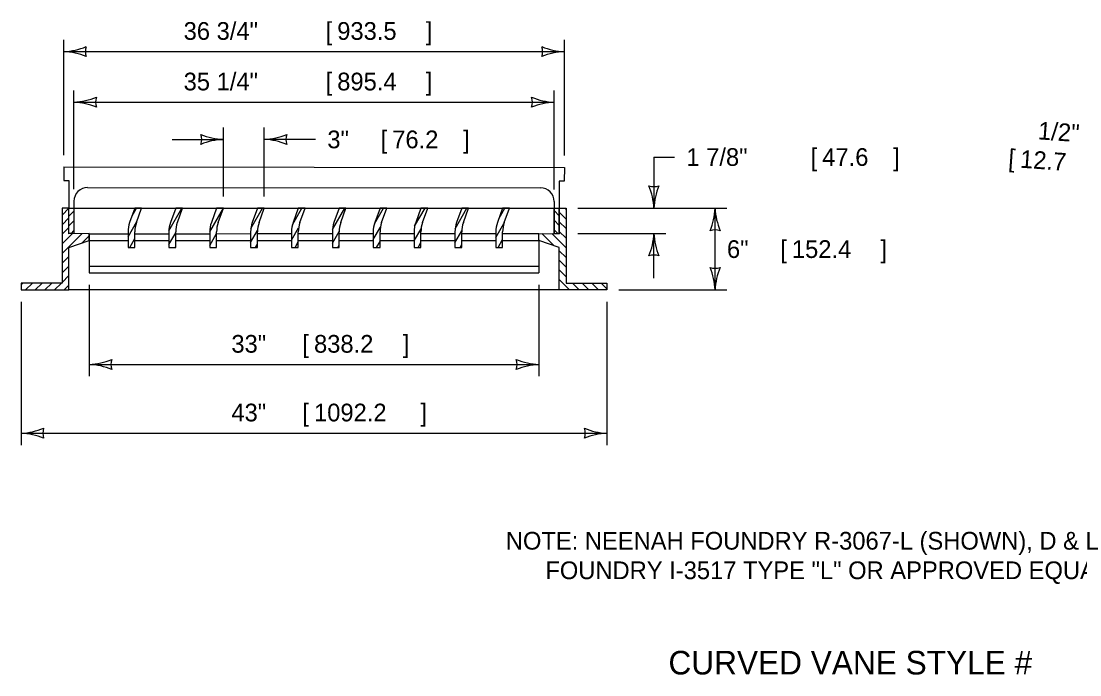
# Model space of a CAD drawing. Extents: x 49991.4 to 50057, y 49987.6 to 50011.4.
# Drawn here: x 50047.642 to 50051.224, y 49994.48 to 49996.693 of the extents above; entities that cross this region are included whole.
import ezdxf

# ---------------------------------------------------------------- set-up
doc = ezdxf.new("R2010")
doc.units = 0
for name, color, linetype in [('Level 1', 7, 'Continuous'), ('Level 2', 7, 'Continuous'), ('Level 3', 7, 'Continuous')]:
    doc.layers.add(name, color=color, linetype=linetype)

msp = doc.modelspace()

# ---------------------------------------------------------------- linework, layer by layer
at = {"layer": 'Level 1'}
for p, q in [((50047.7862, 49996.1991), (50049.4801, 49996.1976)), ((50047.7862, 49996.1991), (50047.7862, 49996.153)), ((50049.4801, 49996.1976), (50049.48, 49996.1515)), ((50047.7862, 49996.153), (50047.8035, 49996.153)), ((50047.8035, 49996.153), (50047.8035, 49996.0594)), ((50049.48, 49996.1515), (50049.4628, 49996.1516)), ((50049.4628, 49996.1516), (50049.4628, 49996.0594)), ((50047.8669, 49996.1299), (50049.3995, 49996.1286)), ((50047.8208, 49996.0838), (50047.8208, 49996.0594)), ((50049.4455, 49996.0825), (50049.4455, 49995.9742)), ((50047.7804, 49996.0364), (50047.8034, 49996.0594)), ((50047.8035, 49996.0321), (50047.8208, 49996.0494)), ((50047.8208, 49996.0594), (50049.4455, 49996.0594)), ((50047.8208, 49996.0594), (50047.8208, 49995.9742)), ((50048.0165, 49996.0313), (50048.0327, 49996.0594)), ((50048.142, 49995.9829), (50048.1862, 49996.0594)), ((50048.2802, 49995.9796), (50048.3263, 49996.0594)), ((50048.4192, 49995.9909), (50048.4587, 49996.0594)), ((50048.5598, 49996.0033), (50048.5922, 49996.0594)), ((50048.6954, 49995.9873), (50048.737, 49996.0594)), ((50048.8373, 49996.0064), (50048.8679, 49996.0594)), ((50048.9736, 49995.9987), (50049.0086, 49996.0594)), ((50049.1104, 49995.9896), (50049.1507, 49996.0594)), ((50049.2583, 49996.0238), (50049.2788, 49996.0594)), ((50049.4455, 49996.0513), (50049.4628, 49996.034)), ((50049.4628, 49996.046), (50049.4858, 49996.023)), ((50049.482, 49996.0594), (50049.4858, 49996.0556)), ((50047.7804, 49996.0038), (50047.8035, 49996.0268)), ((50047.7804, 49995.9712), (50047.8035, 49995.9942)), ((50047.8035, 49995.9995), (50047.8208, 49996.0168)), ((50048.0037, 49995.963), (50048.0335, 49996.0146)), ((50048.5568, 49995.9519), (50048.5809, 49995.9936)), ((50048.8334, 49995.9535), (50048.8578, 49995.9959)), ((50049.2482, 49995.9602), (50049.2755, 49996.0075)), ((50049.4455, 49996.0187), (50049.4628, 49996.0014)), ((50049.4628, 49996.0134), (50049.4858, 49995.9904)), ((50047.7804, 49995.906), (50047.8483, 49995.9738)), ((50047.7804, 49995.9386), (50047.815, 49995.9732)), ((50047.8108, 49995.9742), (50047.8208, 49995.9842)), ((50047.8491, 49995.9421), (50047.8726, 49995.9656)), ((50047.8726, 49995.973), (50048.0039, 49995.9731)), ((50047.8726, 49995.973), (50047.8726, 49995.8404)), ((50048.0095, 49995.9269), (50048.0267, 49995.9568)), ((50048.027, 49995.9731), (50048.142, 49995.9732)), ((50048.142, 49995.9367), (50048.165, 49995.9766)), ((50048.165, 49995.9732), (50048.2802, 49995.9733)), ((50048.2802, 49995.9335), (50048.3033, 49995.9734)), ((50048.3033, 49995.9733), (50048.4187, 49995.9734)), ((50048.4185, 49995.9437), (50048.4417, 49995.9837)), ((50048.4416, 49995.9734), (50048.5568, 49995.9735)), ((50048.5798, 49995.9735), (50048.6951, 49995.9736)), ((50048.6951, 49995.9407), (50048.7181, 49995.9806)), ((50048.7181, 49995.9736), (50048.8335, 49995.9737)), ((50048.8564, 49995.9738), (50048.9718, 49995.9739)), ((50048.9716, 49995.9492), (50048.9953, 49995.9902)), ((50048.9949, 49995.9739), (50049.1101, 49995.974)), ((50049.1099, 49995.9426), (50049.133, 49995.9826)), ((50049.1331, 49995.974), (50049.2484, 49995.9741)), ((50049.2714, 49995.9741), (50049.3937, 49995.9742)), ((50049.4044, 49995.9741), (50049.446, 49995.9325)), ((50049.4376, 49995.9734), (50049.4858, 49995.9252)), ((50049.4455, 49995.9861), (50049.4587, 49995.973)), ((50049.4628, 49995.9808), (50049.4858, 49995.9578)), ((50047.8726, 49995.9499), (50048.0037, 49995.9499)), ((50048.0267, 49995.9499), (50048.142, 49995.9499)), ((50048.1629, 49995.9269), (50048.165, 49995.9305)), ((50048.165, 49995.9499), (50048.2802, 49995.9499)), ((50048.3031, 49995.9269), (50048.3033, 49995.9273)), ((50048.3033, 49995.9499), (50048.4185, 49995.9499)), ((50048.4354, 49995.9269), (50048.4416, 49995.9375)), ((50048.4416, 49995.9499), (50048.5568, 49995.9499)), ((50048.569, 49995.9269), (50048.5798, 49995.9457)), ((50048.5798, 49995.9499), (50048.6951, 49995.9499)), ((50048.7137, 49995.9269), (50048.7181, 49995.9345)), ((50048.7181, 49995.9499), (50048.8334, 49995.9499)), ((50048.8446, 49995.9269), (50048.8564, 49995.9473)), ((50048.8564, 49995.9499), (50048.9716, 49995.9499)), ((50048.9853, 49995.9269), (50048.9947, 49995.943)), ((50048.9947, 49995.9499), (50049.1099, 49995.9499)), ((50049.1274, 49995.9269), (50049.133, 49995.9364)), ((50049.133, 49995.9499), (50049.2482, 49995.9499)), ((50049.2556, 49995.9269), (50049.2712, 49995.954)), ((50049.2712, 49995.9499), (50049.3937, 49995.9499)), ((50049.3937, 49995.9522), (50049.3971, 49995.9488)), ((50049.3937, 49995.9499), (50049.3937, 49995.8404)), ((50047.7804, 49995.8734), (50047.8035, 49995.8965)), ((50049.4628, 49995.9157), (50049.4858, 49995.8926)), ((50047.7804, 49995.8408), (50047.8035, 49995.8639)), ((50047.8726, 49995.8635), (50049.3937, 49995.8635)), ((50049.4628, 49995.8831), (50049.4858, 49995.86)), ((50049.4628, 49995.8505), (50049.4858, 49995.8274)), ((50047.7804, 49995.8082), (50047.8035, 49995.8313)), ((50047.8726, 49995.8404), (50049.3937, 49995.8404)), ((50049.4628, 49995.8179), (50049.4979, 49995.7828)), ((50047.6422, 49995.8003), (50047.6477, 49995.8059)), ((50047.6573, 49995.7828), (50047.6803, 49995.8059)), ((50047.6899, 49995.7828), (50047.7129, 49995.8059)), ((50047.7224, 49995.7828), (50047.7455, 49995.8059)), ((50047.755, 49995.7828), (50047.7781, 49995.8059)), ((50047.7876, 49995.7828), (50047.8035, 49995.7987)), ((50049.4628, 49995.7828), (50047.8035, 49995.7828)), ((50049.4628, 49995.7853), (50049.4653, 49995.7828)), ((50049.5074, 49995.8059), (50049.5305, 49995.7828)), ((50049.54, 49995.8059), (50049.563, 49995.7828)), ((50049.5726, 49995.8059), (50049.5956, 49995.7828)), ((50049.6052, 49995.8059), (50049.6241, 49995.7869))]:
    msp.add_line(p, q, dxfattribs=at)
for points in [[(50047.8035, 49995.7828), (50047.8035, 49995.9269), (50047.8726, 49995.9499), (50047.8726, 49995.9743), (50047.8035, 49995.973), (50047.8035, 49996.0594), (50047.7804, 49996.0594), (50047.7804, 49995.8059), (50047.6422, 49995.8059), (50047.6422, 49995.7828)], [(50047.8035, 49996.0594), (50047.8208, 49996.0594), (50047.8208, 49995.9742), (50047.8035, 49995.9742)], [(50049.4628, 49995.7828), (50049.4628, 49995.9269), (50049.3937, 49995.9499), (50049.3937, 49995.9743), (50049.4628, 49995.973), (50049.4628, 49996.0594), (50049.4858, 49996.0594), (50049.4858, 49995.8059), (50049.6241, 49995.8059), (50049.6241, 49995.7828)], [(50049.4455, 49996.0594), (50049.4628, 49996.0594), (50049.4628, 49995.973), (50049.4455, 49995.973)]]:
    msp.add_lwpolyline(points, close=True, dxfattribs=at)
for points in [[(50048.0323, 49996.0113), (50048.0498, 49996.0594), (50048.0267, 49996.0594), (50048.0267, 49996.0594), (50048.0092, 49996.0113)], [(50048.1706, 49996.0113), (50048.1881, 49996.0594), (50048.165, 49996.0594), (50048.165, 49996.0594), (50048.1475, 49996.0113)], [(50048.3088, 49996.0113), (50048.3263, 49996.0594), (50048.3033, 49996.0594), (50048.3033, 49996.0594), (50048.2858, 49996.0113)], [(50048.4471, 49996.0113), (50048.4646, 49996.0594), (50048.4416, 49996.0594), (50048.4416, 49996.0594), (50048.4241, 49996.0113)], [(50048.5854, 49996.0113), (50048.6029, 49996.0594), (50048.5798, 49996.0594), (50048.5798, 49996.0594), (50048.5624, 49996.0113)], [(50048.7237, 49996.0113), (50048.7412, 49996.0594), (50048.7181, 49996.0594), (50048.7181, 49996.0594), (50048.7006, 49996.0113)], [(50048.8619, 49996.0113), (50048.8794, 49996.0594), (50048.8564, 49996.0594), (50048.8564, 49996.0594), (50048.8389, 49996.0113)], [(50049.0002, 49996.0113), (50049.0177, 49996.0594), (50048.9947, 49996.0594), (50048.9947, 49996.0594), (50048.9772, 49996.0113)], [(50049.1385, 49996.0113), (50049.156, 49996.0594), (50049.133, 49996.0594), (50049.133, 49996.0594), (50049.1155, 49996.0113)], [(50049.2768, 49996.0113), (50049.2943, 49996.0594), (50049.2712, 49996.0594), (50049.2712, 49996.0594), (50049.2537, 49996.0113)], [(50048.0037, 49995.9798), (50048.0037, 49995.9269), (50048.0267, 49995.9269), (50048.0267, 49995.9798)], [(50048.142, 49995.9798), (50048.142, 49995.9269), (50048.165, 49995.9269), (50048.165, 49995.9798)], [(50048.2802, 49995.9798), (50048.2802, 49995.9269), (50048.3033, 49995.9269), (50048.3033, 49995.9798)], [(50048.4185, 49995.9798), (50048.4185, 49995.9269), (50048.4416, 49995.9269), (50048.4416, 49995.9798)], [(50048.5568, 49995.9798), (50048.5568, 49995.9269), (50048.5798, 49995.9269), (50048.5798, 49995.9798)], [(50048.6951, 49995.9798), (50048.6951, 49995.9269), (50048.7181, 49995.9269), (50048.7181, 49995.9798)], [(50048.8334, 49995.9798), (50048.8334, 49995.9269), (50048.8564, 49995.9269), (50048.8564, 49995.9798)], [(50048.9716, 49995.9798), (50048.9716, 49995.9269), (50048.9947, 49995.9269), (50048.9947, 49995.9798)], [(50049.1099, 49995.9798), (50049.1099, 49995.9269), (50049.133, 49995.9269), (50049.133, 49995.9798)], [(50049.2482, 49995.9798), (50049.2482, 49995.9269), (50049.2712, 49995.9269), (50049.2712, 49995.9798)]]:
    msp.add_lwpolyline(points, dxfattribs=at)
for centre, radius, start, end in [((50047.8669, 49996.0838), 0.0461, 89.9504, 180), ((50049.3994, 49996.0825), 0.0461, 0, 89.9504), ((50048.0959, 49995.9798), 0.0922, 160.0169, 180), ((50048.1189, 49995.9798), 0.0922, 160.0169, 180), ((50048.2342, 49995.9798), 0.0922, 160.0169, 180), ((50048.2572, 49995.9798), 0.0922, 160.0169, 180), ((50048.3724, 49995.9798), 0.0922, 160.0169, 180), ((50048.3955, 49995.9798), 0.0922, 160.0169, 180), ((50048.5107, 49995.9798), 0.0922, 160.0169, 180), ((50048.5338, 49995.9798), 0.0922, 160.0169, 180), ((50048.649, 49995.9798), 0.0922, 160.0169, 180), ((50048.672, 49995.9798), 0.0922, 160.0169, 180), ((50048.7873, 49995.9798), 0.0922, 160.0169, 180), ((50048.8103, 49995.9798), 0.0922, 160.0169, 180), ((50048.9255, 49995.9798), 0.0922, 160.0169, 180), ((50048.9486, 49995.9798), 0.0922, 160.0169, 180), ((50049.0638, 49995.9798), 0.0922, 160.0169, 180), ((50049.0869, 49995.9798), 0.0922, 160.0169, 180), ((50049.2021, 49995.9798), 0.0922, 160.0169, 180), ((50049.2251, 49995.9798), 0.0922, 160.0169, 180), ((50049.3404, 49995.9798), 0.0922, 160.0169, 180), ((50049.3634, 49995.9798), 0.0922, 160.0169, 180)]:
    msp.add_arc(centre, radius, start, end, dxfattribs=at)
at = {"layer": 'Level 3'}
for p, q in [((50047.7862, 49996.2391), (50047.7862, 49996.6296)), ((50049.4801, 49996.2376), (50049.4801, 49996.6296)), ((50047.7862, 49996.5896), (50049.4801, 49996.5896)), ((50047.8208, 49996.1238), (50047.8208, 49996.4585)), ((50049.4455, 49996.1225), (50049.4455, 49996.4585)), ((50047.8208, 49996.4184), (50049.4455, 49996.4184)), ((50048.3263, 49996.0994), (50048.3263, 49996.3325)), ((50048.4646, 49996.0994), (50048.4646, 49996.3325)), ((50048.1529, 49996.2925), (50048.3263, 49996.2925)), ((50048.6381, 49996.2925), (50048.4646, 49996.2925)), ((50049.7831, 49996.2328), (50049.7831, 49996.0594)), ((50049.7831, 49996.2328), (50049.8531, 49996.2328)), ((50049.5258, 49996.0594), (50050.0303, 49996.0594)), ((50049.9903, 49995.7828), (50049.9903, 49996.0594)), ((50049.5258, 49995.9742), (50049.823, 49995.9742)), ((50049.7831, 49995.8228), (50049.7831, 49995.9742)), ((50047.8726, 49995.8005), (50047.8726, 49995.4905)), ((50049.3937, 49995.8005), (50049.3937, 49995.4905)), ((50049.6641, 49995.7828), (50050.0303, 49995.7828)), ((50047.6422, 49995.7428), (50047.6422, 49995.2578)), ((50049.6241, 49995.7428), (50049.6241, 49995.2578)), ((50047.8726, 49995.5304), (50049.3937, 49995.5304)), ((50047.6422, 49995.2978), (50049.6241, 49995.2978))]:
    msp.add_line(p, q, dxfattribs=at)
for centre, radius, start, end in [((50047.7747, 49996.8224), 0.233, 272.8273, 292.0772), ((50047.9144, 49996.5896), 0.0548, 162.1388, 197.8612), ((50049.4892, 49996.8118), 0.2223, 247.456, 267.6395), ((50049.3519, 49996.5896), 0.0548, 342.1388, 17.8612), ((50047.7771, 49996.3675), 0.2223, 67.456, 87.6395), ((50049.4916, 49996.3569), 0.233, 92.8273, 112.0772), ((50047.8093, 49996.6512), 0.233, 272.8273, 292.0772), ((50047.949, 49996.4184), 0.0548, 162.1388, 197.8612), ((50049.4547, 49996.6406), 0.2223, 247.456, 267.6395), ((50049.3173, 49996.4184), 0.0548, 342.1388, 17.8612), ((50047.8116, 49996.1963), 0.2223, 67.456, 87.6395), ((50049.457, 49996.1857), 0.233, 92.8273, 112.0772), ((50048.3355, 49996.5146), 0.2223, 247.456, 267.6395), ((50048.1981, 49996.2925), 0.0548, 342.1388, 17.8612), ((50048.3378, 49996.0598), 0.233, 92.8273, 112.0772), ((50048.4531, 49996.5252), 0.233, 272.8273, 292.0772), ((50048.4555, 49996.0703), 0.2223, 67.456, 87.6395), ((50048.5928, 49996.2925), 0.0548, 162.1388, 197.8612), ((50049.7831, 49996.1876), 0.0548, 252.1388, 287.8612), ((50049.5504, 49996.0479), 0.233, 2.8273, 22.0772), ((50050.0052, 49996.0502), 0.2223, 157.456, 177.6395), ((50049.7682, 49996.0685), 0.2223, 337.456, 357.6395), ((50050.223, 49996.0709), 0.233, 182.8273, 202.0772), ((50049.561, 49995.9834), 0.2223, 337.456, 357.6395), ((50050.0158, 49995.9857), 0.233, 182.8273, 202.0772), ((50049.9903, 49995.9312), 0.0548, 72.1388, 107.8612), ((50049.7831, 49995.846), 0.0548, 72.1388, 107.8612), ((50049.9903, 49995.911), 0.0548, 252.1388, 287.8612), ((50049.7576, 49995.7713), 0.233, 2.8273, 22.0772), ((50050.2124, 49995.7737), 0.2223, 157.456, 177.6395), ((50047.8611, 49995.7631), 0.233, 272.8273, 292.0772), ((50047.8635, 49995.3083), 0.2223, 67.456, 87.6395), ((50048.0008, 49995.5304), 0.0548, 162.1388, 197.8612), ((50049.4028, 49995.7526), 0.2223, 247.456, 267.6395), ((50049.2654, 49995.5304), 0.0548, 342.1388, 17.8612), ((50049.4052, 49995.2977), 0.233, 92.8273, 112.0772), ((50047.6307, 49995.5305), 0.233, 272.8273, 292.0772), ((50047.7704, 49995.2978), 0.0548, 162.1388, 197.8612), ((50049.6333, 49995.5199), 0.2223, 247.456, 267.6395), ((50049.4959, 49995.2978), 0.0548, 342.1388, 17.8612), ((50047.633, 49995.0757), 0.2223, 67.456, 87.6395), ((50049.6356, 49995.0651), 0.233, 92.8273, 112.0772)]:
    msp.add_arc(centre, radius, start, end, dxfattribs=at)

# ---------------------------------------------------------------- texts
at = {"layer": 'Level 2'}
for s, height, p in [('36 3/4" ', 0.06, (50048.1919, 49996.6296)), ('[', 0.06, (50048.6719, 49996.6296)), ('933.5', 0.06, (50048.7116, 49996.6296)), (']', 0.06, (50049.0116, 49996.6296)), ('35 1/4" ', 0.06, (50048.1919, 49996.4584)), ('[', 0.06, (50048.6719, 49996.4584)), ('895.4', 0.06, (50048.7116, 49996.4584)), (']', 0.06, (50049.0116, 49996.4584)), ('3" ', 0.06, (50048.6781, 49996.2625)), ('[', 0.06, (50048.8581, 49996.2625)), ('76.2', 0.06, (50048.8977, 49996.2625)), (']', 0.06, (50049.1377, 49996.2625)), ('6" ', 0.06, (50050.0303, 49995.8911)), ('[', 0.06, (50050.2103, 49995.8911)), ('152.4', 0.06, (50050.25, 49995.8911)), (']', 0.06, (50050.55, 49995.8911)), ('[', 0.06, (50048.5935, 49995.5704)), (']', 0.06, (50048.9331, 49995.5704)), ('33" ', 0.06, (50048.3535, 49995.5704)), ('838.2', 0.06, (50048.6331, 49995.5704)), ('43" ', 0.06, (50048.3535, 49995.3378)), ('[', 0.06, (50048.5935, 49995.3378)), ('1092.2', 0.06, (50048.6331, 49995.3378)), (']', 0.06, (50048.9931, 49995.3378)), ('NOTE: NEENAH FOUNDRY R-3067-L (SHOWN), D & L', 0.06, (50049.2821, 49994.9037)), ('      FOUNDRY I-3517 TYPE "L" OR APPROVED EQUAL', 0.06, (50049.2821, 49994.8037)), ('CURVED VANE STYLE #', 0.08, (50049.8324, 49994.4809))]:
    msp.add_text(s, height=height, dxfattribs=at).set_placement(p)
for s, rotation, p in [('1/2"', 356, (50051.0813, 49996.2929)), ('1 7/8" ', 360, (50049.8931, 49996.2028)), ('[', 360, (50050.3131, 49996.2028)), ('47.6', 360, (50050.3528, 49996.2028)), (']', 360, (50050.5928, 49996.2028)), ('[', 356, (50050.981, 49996.1997)), ('12.7', 356, (50051.0206, 49996.1969))]:
    msp.add_text(s, height=0.06, rotation=rotation, dxfattribs=at).set_placement(p)

doc.saveas('drawing.dxf')
